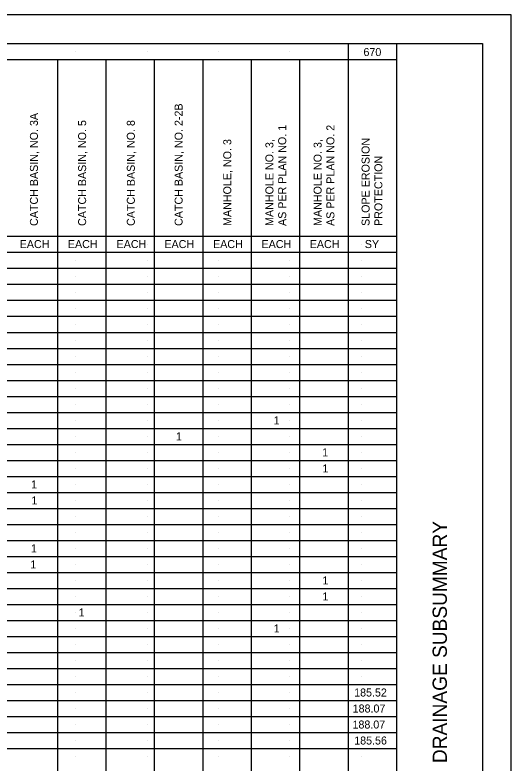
# Model space of a CAD drawing. Extents: x 2073163.9 to 2073197.9, y 634076.5 to 634098.5.
# Drawn here: x 2073189.26 to 2073197.95, y 634085.46 to 634098.55 of the extents above; entities that cross this region are included whole.
import ezdxf

# ---------------------------------------------------------------- set-up
doc = ezdxf.new("R2010")
doc.units = 0
for name, color, linetype in [('Default', 7, 'Continuous'), ('SH_Border', 7, 'Continuous'), ('SH_Cut_Line', 7, 'Continuous'), ('SH_Data', 7, 'Continuous'), ('SH_Text', 7, 'Continuous')]:
    doc.layers.add(name, color=color, linetype=linetype)

msp = doc.modelspace()

# ---------------------------------------------------------------- linework, layer by layer
at = {"layer": 'SH_Border'}
msp.add_line((2073195.946, 634077.05), (2073195.946, 634098.05), dxfattribs=at)
msp.add_lwpolyline([(2073165.446, 634098.05), (2073197.446, 634098.05), (2073197.446, 634077.05), (2073165.446, 634077.05)], close=True, dxfattribs=at)
at = {"layer": 'SH_Cut_Line'}
msp.add_lwpolyline([(2073163.946, 634076.55), (2073197.946, 634076.55), (2073197.946, 634098.55), (2073163.946, 634098.55)], close=True, dxfattribs=at)
at = {"layer": 'SH_Data'}
for p, q in [((2073190.321, 634097.91), (2073190.321, 634097.91)), ((2073191.571, 634097.91), (2073191.571, 634097.91)), ((2073192.821, 634097.91), (2073192.821, 634097.91)), ((2073194.071, 634097.91), (2073194.071, 634097.91)), ((2073195.321, 634097.91), (2073195.321, 634097.91)), ((2073171.345, 634097.77), (2073195.946, 634097.77)), ((2073171.345, 634094.682), (2073195.945, 634094.682)), ((2073190.321, 634094.538), (2073190.321, 634094.538)), ((2073191.571, 634094.538), (2073191.571, 634094.538)), ((2073192.821, 634094.538), (2073192.821, 634094.538)), ((2073194.071, 634094.538), (2073194.071, 634094.538)), ((2073195.321, 634094.538), (2073195.321, 634094.538)), ((2073165.446, 634094.398), (2073195.946, 634094.398)), ((2073190.321, 634094.258), (2073190.321, 634094.258)), ((2073191.571, 634094.258), (2073191.571, 634094.258)), ((2073192.821, 634094.258), (2073192.821, 634094.258)), ((2073194.071, 634094.258), (2073194.071, 634094.258)), ((2073195.321, 634094.258), (2073195.321, 634094.258)), ((2073165.44, 634094.118), (2073195.948, 634094.118)), ((2073190.321, 634093.978), (2073190.321, 634093.978)), ((2073191.571, 634093.978), (2073191.571, 634093.978)), ((2073192.821, 634093.978), (2073192.821, 634093.978)), ((2073194.071, 634093.978), (2073194.071, 634093.978)), ((2073195.321, 634093.978), (2073195.321, 634093.978)), ((2073165.45, 634093.838), (2073195.947, 634093.838)), ((2073190.321, 634093.698), (2073190.321, 634093.698)), ((2073191.571, 634093.698), (2073191.571, 634093.698)), ((2073192.821, 634093.698), (2073192.821, 634093.698)), ((2073194.071, 634093.698), (2073194.071, 634093.698)), ((2073195.321, 634093.698), (2073195.321, 634093.698)), ((2073165.45, 634093.558), (2073195.947, 634093.558)), ((2073190.321, 634093.418), (2073190.321, 634093.418)), ((2073191.571, 634093.418), (2073191.571, 634093.418)), ((2073192.821, 634093.418), (2073192.821, 634093.418)), ((2073194.071, 634093.418), (2073194.071, 634093.418)), ((2073195.321, 634093.418), (2073195.321, 634093.418)), ((2073165.447, 634093.278), (2073195.949, 634093.278)), ((2073190.321, 634093.138), (2073190.321, 634093.138)), ((2073191.571, 634093.138), (2073191.571, 634093.138)), ((2073192.821, 634093.138), (2073192.821, 634093.138)), ((2073194.071, 634093.138), (2073194.071, 634093.138)), ((2073195.321, 634093.138), (2073195.321, 634093.138)), ((2073165.444, 634092.998), (2073195.947, 634092.998)), ((2073190.321, 634092.858), (2073190.321, 634092.858)), ((2073191.571, 634092.858), (2073191.571, 634092.858)), ((2073192.821, 634092.858), (2073192.821, 634092.858)), ((2073194.071, 634092.858), (2073194.071, 634092.858)), ((2073195.321, 634092.858), (2073195.321, 634092.858)), ((2073165.454, 634092.718), (2073195.947, 634092.718)), ((2073190.321, 634092.578), (2073190.321, 634092.578)), ((2073191.571, 634092.578), (2073191.571, 634092.578)), ((2073192.821, 634092.578), (2073192.821, 634092.578)), ((2073194.071, 634092.578), (2073194.071, 634092.578)), ((2073195.321, 634092.578), (2073195.321, 634092.578)), ((2073165.45, 634092.438), (2073195.943, 634092.438)), ((2073190.321, 634092.298), (2073190.321, 634092.298)), ((2073191.571, 634092.298), (2073191.571, 634092.298)), ((2073192.821, 634092.298), (2073192.821, 634092.298)), ((2073194.071, 634092.298), (2073194.071, 634092.298)), ((2073195.321, 634092.298), (2073195.321, 634092.298)), ((2073165.448, 634092.158), (2073195.943, 634092.158)), ((2073190.321, 634092.018), (2073190.321, 634092.018)), ((2073191.571, 634092.018), (2073191.571, 634092.018)), ((2073192.821, 634092.018), (2073192.821, 634092.018)), ((2073194.071, 634092.018), (2073194.071, 634092.018)), ((2073195.321, 634092.018), (2073195.321, 634092.018)), ((2073165.448, 634091.878), (2073195.943, 634091.878)), ((2073190.321, 634091.738), (2073190.321, 634091.738)), ((2073191.571, 634091.738), (2073191.571, 634091.738)), ((2073192.821, 634091.738), (2073192.821, 634091.738)), ((2073194.071, 634091.738), (2073194.071, 634091.738)), ((2073195.321, 634091.738), (2073195.321, 634091.738)), ((2073165.448, 634091.598), (2073195.948, 634091.598)), ((2073190.321, 634091.458), (2073190.321, 634091.458)), ((2073191.571, 634091.458), (2073191.571, 634091.458)), ((2073192.821, 634091.458), (2073192.821, 634091.458)), ((2073194.071, 634091.458), (2073194.071, 634091.458)), ((2073195.321, 634091.458), (2073195.321, 634091.458)), ((2073165.451, 634091.318), (2073195.939, 634091.318)), ((2073165.451, 634091.318), (2073195.944, 634091.318)), ((2073190.321, 634091.178), (2073190.321, 634091.178)), ((2073191.571, 634091.178), (2073191.571, 634091.178)), ((2073192.821, 634091.178), (2073192.821, 634091.178)), ((2073194.071, 634091.178), (2073194.071, 634091.178)), ((2073195.321, 634091.178), (2073195.321, 634091.178)), ((2073165.448, 634091.038), (2073195.944, 634091.038)), ((2073190.321, 634090.898), (2073190.321, 634090.898)), ((2073191.571, 634090.898), (2073191.571, 634090.898)), ((2073192.821, 634090.898), (2073192.821, 634090.898)), ((2073194.071, 634090.898), (2073194.071, 634090.898)), ((2073195.321, 634090.898), (2073195.321, 634090.898)), ((2073165.445, 634090.758), (2073195.942, 634090.758)), ((2073190.321, 634090.618), (2073190.321, 634090.618)), ((2073191.571, 634090.618), (2073191.571, 634090.618)), ((2073192.821, 634090.618), (2073192.821, 634090.618)), ((2073194.071, 634090.618), (2073194.071, 634090.618)), ((2073195.321, 634090.618), (2073195.321, 634090.618)), ((2073165.442, 634090.478), (2073195.946, 634090.478)), ((2073190.321, 634090.338), (2073190.321, 634090.338)), ((2073191.571, 634090.338), (2073191.571, 634090.338)), ((2073192.821, 634090.338), (2073192.821, 634090.338)), ((2073194.071, 634090.338), (2073194.071, 634090.338)), ((2073195.321, 634090.338), (2073195.321, 634090.338)), ((2073165.442, 634090.198), (2073195.946, 634090.198)), ((2073190.321, 634090.058), (2073190.321, 634090.058)), ((2073191.571, 634090.058), (2073191.571, 634090.058)), ((2073192.821, 634090.058), (2073192.821, 634090.058)), ((2073194.071, 634090.058), (2073194.071, 634090.058)), ((2073195.321, 634090.058), (2073195.321, 634090.058)), ((2073165.446, 634089.918), (2073195.946, 634089.918)), ((2073190.321, 634089.778), (2073190.321, 634089.778)), ((2073191.571, 634089.778), (2073191.571, 634089.778)), ((2073192.821, 634089.778), (2073192.821, 634089.778)), ((2073194.071, 634089.778), (2073194.071, 634089.778)), ((2073195.321, 634089.778), (2073195.321, 634089.778)), ((2073165.446, 634089.638), (2073195.946, 634089.638)), ((2073190.321, 634089.498), (2073190.321, 634089.498)), ((2073191.571, 634089.498), (2073191.571, 634089.498)), ((2073192.821, 634089.498), (2073192.821, 634089.498)), ((2073194.071, 634089.498), (2073194.071, 634089.498)), ((2073195.321, 634089.498), (2073195.321, 634089.498)), ((2073165.446, 634089.358), (2073195.946, 634089.358)), ((2073190.321, 634089.218), (2073190.321, 634089.218)), ((2073191.571, 634089.218), (2073191.571, 634089.218)), ((2073192.821, 634089.218), (2073192.821, 634089.218)), ((2073194.071, 634089.218), (2073194.071, 634089.218)), ((2073195.321, 634089.218), (2073195.321, 634089.218)), ((2073165.446, 634089.078), (2073195.946, 634089.078)), ((2073190.321, 634088.938), (2073190.321, 634088.938)), ((2073191.571, 634088.938), (2073191.571, 634088.938)), ((2073192.821, 634088.938), (2073192.821, 634088.938)), ((2073194.071, 634088.938), (2073194.071, 634088.938)), ((2073195.321, 634088.938), (2073195.321, 634088.938)), ((2073165.446, 634088.798), (2073195.946, 634088.798)), ((2073190.321, 634088.658), (2073190.321, 634088.658)), ((2073191.571, 634088.658), (2073191.571, 634088.658)), ((2073192.821, 634088.658), (2073192.821, 634088.658)), ((2073194.071, 634088.658), (2073194.071, 634088.658)), ((2073195.321, 634088.658), (2073195.321, 634088.658)), ((2073165.446, 634088.518), (2073195.946, 634088.518)), ((2073190.321, 634088.378), (2073190.321, 634088.378)), ((2073191.571, 634088.378), (2073191.571, 634088.378)), ((2073192.821, 634088.378), (2073192.821, 634088.378)), ((2073194.071, 634088.378), (2073194.071, 634088.378)), ((2073195.321, 634088.378), (2073195.321, 634088.378)), ((2073165.446, 634088.238), (2073195.946, 634088.238)), ((2073190.321, 634088.098), (2073190.321, 634088.098)), ((2073191.571, 634088.098), (2073191.571, 634088.098)), ((2073192.821, 634088.098), (2073192.821, 634088.098)), ((2073194.071, 634088.098), (2073194.071, 634088.098)), ((2073195.321, 634088.098), (2073195.321, 634088.098)), ((2073165.446, 634087.958), (2073195.946, 634087.958)), ((2073190.321, 634087.818), (2073190.321, 634087.818)), ((2073191.571, 634087.818), (2073191.571, 634087.818)), ((2073192.821, 634087.818), (2073192.821, 634087.818)), ((2073194.071, 634087.818), (2073194.071, 634087.818)), ((2073195.321, 634087.818), (2073195.321, 634087.818)), ((2073165.446, 634087.678), (2073195.946, 634087.678)), ((2073190.321, 634087.538), (2073190.321, 634087.538)), ((2073191.571, 634087.538), (2073191.571, 634087.538)), ((2073192.821, 634087.538), (2073192.821, 634087.538)), ((2073194.071, 634087.538), (2073194.071, 634087.538)), ((2073195.321, 634087.538), (2073195.321, 634087.538)), ((2073165.446, 634087.398), (2073195.946, 634087.398)), ((2073190.321, 634087.258), (2073190.321, 634087.258)), ((2073191.571, 634087.258), (2073191.571, 634087.258)), ((2073192.821, 634087.258), (2073192.821, 634087.258)), ((2073194.071, 634087.258), (2073194.071, 634087.258)), ((2073195.321, 634087.258), (2073195.321, 634087.258)), ((2073165.446, 634087.118), (2073195.946, 634087.118)), ((2073190.321, 634086.978), (2073190.321, 634086.978)), ((2073191.571, 634086.978), (2073191.571, 634086.978)), ((2073192.821, 634086.978), (2073192.821, 634086.978)), ((2073194.071, 634086.978), (2073194.071, 634086.978)), ((2073195.321, 634086.978), (2073195.321, 634086.978)), ((2073165.446, 634086.838), (2073195.946, 634086.838)), ((2073190.321, 634086.698), (2073190.321, 634086.698)), ((2073191.571, 634086.698), (2073191.571, 634086.698)), ((2073192.821, 634086.698), (2073192.821, 634086.698)), ((2073194.071, 634086.698), (2073194.071, 634086.698)), ((2073195.321, 634086.698), (2073195.321, 634086.698)), ((2073165.446, 634086.558), (2073195.946, 634086.558)), ((2073190.321, 634086.418), (2073190.321, 634086.418)), ((2073191.571, 634086.418), (2073191.571, 634086.418)), ((2073192.821, 634086.418), (2073192.821, 634086.418)), ((2073194.071, 634086.418), (2073194.071, 634086.418)), ((2073195.321, 634086.418), (2073195.321, 634086.418)), ((2073165.446, 634086.278), (2073195.946, 634086.278)), ((2073190.321, 634086.138), (2073190.321, 634086.138)), ((2073191.571, 634086.138), (2073191.571, 634086.138)), ((2073192.821, 634086.138), (2073192.821, 634086.138)), ((2073194.071, 634086.138), (2073194.071, 634086.138)), ((2073195.321, 634086.138), (2073195.321, 634086.138)), ((2073165.446, 634085.998), (2073195.946, 634085.998)), ((2073190.321, 634085.858), (2073190.321, 634085.858)), ((2073191.571, 634085.858), (2073191.571, 634085.858)), ((2073192.821, 634085.858), (2073192.821, 634085.858)), ((2073194.071, 634085.858), (2073194.071, 634085.858)), ((2073195.321, 634085.858), (2073195.321, 634085.858)), ((2073165.446, 634085.718), (2073195.946, 634085.718)), ((2073190.321, 634085.578), (2073190.321, 634085.578)), ((2073191.571, 634085.578), (2073191.571, 634085.578)), ((2073192.821, 634085.578), (2073192.821, 634085.578)), ((2073194.071, 634085.578), (2073194.071, 634085.578)), ((2073195.321, 634085.578), (2073195.321, 634085.578))]:
    msp.add_line(p, q, dxfattribs=at)
at = {"layer": 'SH_Text'}
for p, q in [((2073195.097, 634077.05), (2073195.097, 634098.05)), ((2073190.008, 634077.05), (2073190.008, 634097.77)), ((2073190.856, 634077.05), (2073190.856, 634097.77)), ((2073191.704, 634077.05), (2073191.704, 634097.77)), ((2073192.552, 634077.05), (2073192.552, 634097.77)), ((2073193.401, 634077.05), (2073193.401, 634097.77)), ((2073194.249, 634077.05), (2073194.249, 634097.77))]:
    msp.add_line(p, q, dxfattribs=at)

# ---------------------------------------------------------------- texts
at = {"layer": 'Default'}
msp.add_text('DRAINAGE SUBSUMMARY', height=0.25, rotation=90, dxfattribs=at).set_placement((2073196.822, 634085.463))
at = {"layer": 'SH_Text'}
for s, rotation, p in [('670', 0.0001, (2073195.361, 634097.831)), ('CATCH BASIN, NO. 2-2B', 90.0001, (2073192.194, 634094.859)), ('CATCH BASIN, NO. 3A', 90.0001, (2073189.66, 634094.859)), ('CATCH BASIN, NO. 5', 90.0001, (2073190.504, 634094.859)), ('CATCH BASIN, NO. 8', 90.0001, (2073191.357, 634094.859)), ('AS PER PLAN NO. 1', 90.0001, (2073194.008, 634094.859)), ('AS PER PLAN NO. 2', 90.0001, (2073194.852, 634094.859)), ('MANHOLE, NO. 3', 90.0001, (2073193.046, 634094.859)), ('MANHOLE NO. 3,', 90.0001, (2073193.784, 634094.859)), ('MANHOLE NO. 3,', 90.0001, (2073194.628, 634094.859)), ('SLOPE EROSION', 90.0001, (2073195.468, 634094.859)), ('PROTECTION', 90.0001, (2073195.692, 634094.859)), ('EACH', 0.0001, (2073189.341, 634094.472)), ('EACH', 0.0001, (2073190.185, 634094.472)), ('EACH', 0.0001, (2073191.038, 634094.472)), ('EACH', 0.0001, (2073191.875, 634094.472)), ('EACH', 0.0001, (2073192.727, 634094.472)), ('EACH', 0.0001, (2073193.576, 634094.472)), ('EACH', 0.0001, (2073194.42, 634094.472)), ('SY', 0.0001, (2073195.385, 634094.472)), ('1', 0.0001, (2073193.787, 634091.388)), ('1', 0.0001, (2073192.078, 634091.108)), ('1', 0.0001, (2073194.638, 634090.828)), ('1', 0.0001, (2073194.642, 634090.548)), ('1', 0.0001, (2073189.541, 634090.268)), ('1', 0.0001, (2073189.546, 634089.988)), ('1', 0.0001, (2073189.537, 634089.148)), ('1', 0.0001, (2073189.527, 634088.868)), ('1', 0.0001, (2073194.642, 634088.588)), ('1', 0.0001, (2073194.642, 634088.308)), ('1', 0.0001, (2073190.372, 634088.028)), ('1', 0.0001, (2073193.789, 634087.748)), ('185.52', 0.0001, (2073195.198, 634086.628)), ('188.07', 0.0001, (2073195.172, 634086.348)), ('188.07', 0.0001, (2073195.169, 634086.068)), ('185.56', 0.0001, (2073195.199, 634085.788))]:
    msp.add_text(s, height=0.14, rotation=rotation, dxfattribs=at).set_placement(p)

doc.saveas('drawing.dxf')
